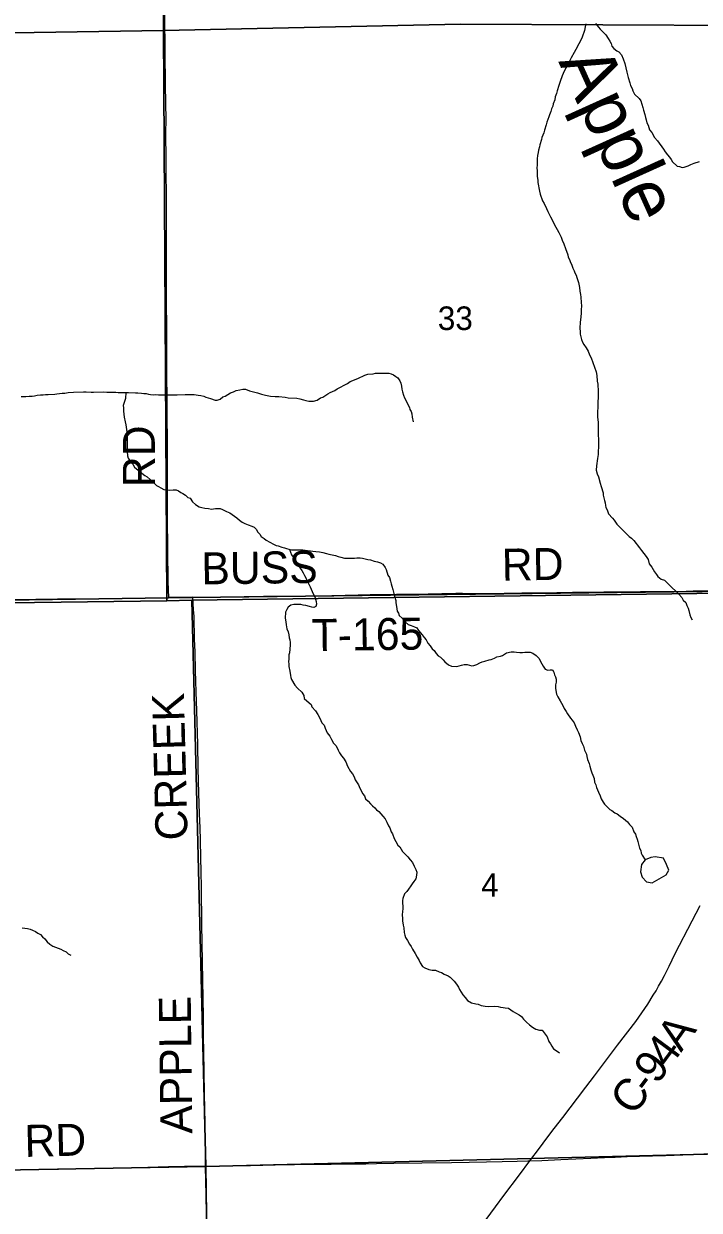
# Model space of a CAD drawing. Extents: x 1985906 to 2360102, y 891258 to 1222054.
# Drawn here: x 2149073 to 2155412, y 987975 to 999101 of the extents above; entities that cross this region are included whole.
import ezdxf

# ---------------------------------------------------------------- set-up
doc = ezdxf.new("R2010")
doc.units = 0
for name, color, linetype in [('GM_X_County_Road', 7, 'Continuous'), ('GM_X_County_Road_Text', 7, 'Continuous'), ('GM_X_Minor_Lake', 7, 'Continuous'), ('GM_X_Minor_River', 7, 'Continuous'), ('GM_X_Minor_River_Text', 7, 'Continuous'), ('GM_X_Section', 7, 'Continuous'), ('GM_X_Section_Text', 7, 'Continuous'), ('GM_X_Township', 7, 'Continuous'), ('GM_X_Township_Road', 7, 'Continuous'), ('GM_X_Township_Road_Text', 7, 'Continuous')]:
    doc.layers.add(name, color=color, linetype=linetype)

msp = doc.modelspace()

# ---------------------------------------------------------------- linework, layer by layer
at = {"layer": 'GM_X_County_Road'}
for points in [[(2150433, 993720), (2150428, 993869), (2150426, 994164), (2150423, 994476), (2150422, 994673), (2150422, 994820), (2150421, 994951), (2150421, 995033), (2150421, 995181), (2150418, 995427), (2150419, 995509), (2150419, 995607), (2150417, 995788), (2150417, 995935), (2150416, 996116), (2150413, 996624), (2150413, 996985), (2150411, 997116), (2150412, 997248), (2150411, 997510), (2150409, 997690), (2150409, 997838), (2150407, 998067), (2150408, 998214), (2150406, 998345), (2150403, 998542), (2150402, 998643), (2150401, 998718), (2150401, 998802), (2150400, 998895), (2150400, 998937), (2150398, 999082), (2150396, 999279)], [(2150661, 993723), (2150570, 993722), (2150439, 993720), (2150433, 993720)], [(2150779, 988390), (2150777, 988544), (2150775, 988675), (2150774, 988790), (2150769, 989068), (2150767, 989281), (2150763, 989461), (2150761, 989610), (2150758, 989790), (2150754, 990134), (2150748, 990479), (2150745, 990659), (2150740, 991003), (2150737, 991151), (2150734, 991281), (2150730, 991445), (2150727, 991560), (2150722, 991691), (2150717, 991887), (2150711, 992117), (2150705, 992346), (2150696, 992658), (2150690, 992838), (2150685, 993036), (2150680, 993212), (2150676, 993330), (2150671, 993542), (2150667, 993607), (2150664, 993662), (2150661, 993723)], [(2153822, 988440), (2153911, 988558), (2153981, 988650), (2154050, 988741), (2154130, 988845), (2154268, 989028), (2154348, 989130), (2154429, 989237), (2154645, 989524), (2154815, 989746), (2154872, 989826), (2154928, 989907), (2154980, 989991), (2155007, 990034), (2155029, 990076), (2155057, 990125), (2155084, 990177), (2155129, 990265), (2155187, 990383), (2155344, 990689), (2155419, 990834)], [(2153822, 988440), (2153934, 988443), (2154114, 988451), (2154393, 988464), (2154458, 988468), (2154523, 988470), (2154621, 988474), (2154735, 988478), (2154850, 988482), (2155095, 988490), (2155259, 988496), (2155456, 988504), (2155619, 988508), (2155849, 988518), (2155980, 988523), (2156229, 988529)], [(2150779, 988390), (2150956, 988393), (2151202, 988396), (2151431, 988401), (2151612, 988405), (2151710, 988408), (2151776, 988409), (2151956, 988409), (2152136, 988410), (2152218, 988411), (2152284, 988412), (2152382, 988414), (2152546, 988416), (2152808, 988419), (2153087, 988423), (2153251, 988426), (2153415, 988429), (2153562, 988432), (2153704, 988437), (2153803, 988440), (2153822, 988440)], [(2152855, 987119), (2152883, 987159), (2153063, 987413), (2153149, 987533), (2153294, 987731), (2153411, 987889), (2153500, 988008), (2153577, 988113), (2153725, 988309), (2153822, 988440)], [(2149023, 988355), (2149154, 988358), (2149399, 988362), (2149594, 988366), (2149710, 988368), (2149875, 988371), (2150022, 988374), (2150136, 988377), (2150333, 988382), (2150431, 988385), (2150580, 988388), (2150710, 988389), (2150779, 988390)], [(2150836, 984837), (2150838, 984849), (2150839, 984859), (2150840, 984877), (2150842, 985003), (2150837, 985265), (2150836, 985446), (2150835, 985577), (2150834, 985675), (2150832, 985823), (2150829, 985970), (2150821, 986314), (2150818, 986445), (2150816, 986577), (2150813, 986724), (2150808, 986888), (2150798, 987412), (2150791, 987773), (2150784, 988117), (2150782, 988249), (2150779, 988390)]]:
    msp.add_lwpolyline(points, dxfattribs=at)
at = {"layer": 'GM_X_Minor_Lake'}
for points in [[(2154904, 991262), (2154870, 991216), (2154860, 991149), (2154875, 991099), (2154917, 991056), (2154969, 991046), (2155102, 991119), (2155126, 991163), (2155104, 991217), (2155075, 991277), (2154997, 991289), (2154957, 991284)], [(2154957, 991284), (2154904, 991262)]]:
    msp.add_lwpolyline(points, dxfattribs=at)
at = {"layer": 'GM_X_Minor_River'}
for points in [[(2154347, 999101), (2154341, 999071), (2154334, 999039), (2154330, 999019), (2154320, 998995), (2154312, 998975), (2154298, 998942), (2154283, 998914), (2154253, 998858), (2154237, 998830), (2154210, 998781), (2154194, 998751), (2154158, 998685), (2154143, 998655), (2154125, 998612), (2154107, 998560), (2154094, 998522), (2154078, 998472), (2154072, 998448), (2154058, 998415), (2154055, 998389), (2154041, 998349), (2154037, 998329), (2154025, 998303), (2154019, 998279), (2154006, 998248), (2154000, 998228), (2153982, 998178), (2153974, 998154), (2153959, 998104), (2153953, 998078), (2153935, 998035), (2153931, 998015), (2153916, 997967), (2153914, 997947), (2153904, 997917), (2153900, 997895), (2153894, 997864), (2153891, 997834), (2153891, 997804), (2153889, 997774), (2153887, 997750), (2153890, 997722), (2153892, 997692), (2153892, 997668), (2153896, 997634), (2153898, 997612), (2153903, 997582), (2153905, 997561), (2153911, 997531), (2153919, 997503), (2153941, 997441), (2153956, 997415), (2153978, 997367), (2153992, 997341), (2154016, 997291), (2154033, 997255), (2154053, 997215), (2154077, 997173), (2154093, 997143), (2154116, 997099), (2154124, 997073), (2154142, 997037), (2154156, 996993), (2154177, 996933), (2154183, 996913), (2154195, 996891), (2154199, 996871), (2154216, 996837), (2154224, 996808), (2154238, 996784), (2154244, 996764), (2154256, 996742), (2154264, 996720), (2154279, 996674), (2154287, 996628), (2154291, 996594), (2154297, 996562), (2154300, 996536), (2154304, 996488), (2154306, 996456), (2154304, 996417), (2154303, 996389), (2154301, 996349), (2154295, 996303), (2154292, 996247), (2154294, 996213), (2154294, 996189), (2154306, 996140), (2154315, 996116), (2154327, 996094), (2154351, 996062), (2154369, 996032), (2154383, 995996), (2154398, 995968), (2154414, 995926), (2154444, 995836)], [(2154439, 999104), (2154467, 999070), (2154483, 999050), (2154514, 999018), (2154534, 998996), (2154556, 998962), (2154572, 998936), (2154584, 998916), (2154592, 998892), (2154609, 998868), (2154637, 998846), (2154657, 998836), (2154681, 998810), (2154697, 998772), (2154713, 998728), (2154724, 998686), (2154732, 998648), (2154744, 998596), (2154761, 998546), (2154767, 998521), (2154781, 998493), (2154787, 998473), (2154805, 998441), (2154848, 998399), (2154864, 998377), (2154874, 998347), (2154882, 998315), (2154888, 998289), (2154901, 998249), (2154907, 998223), (2154913, 998201), (2154921, 998173), (2154931, 998151), (2154946, 998107), (2154966, 998081), (2154992, 998035), (2155020, 998003), (2155035, 997981), (2155061, 997947), (2155075, 997925), (2155093, 997901), (2155113, 997873), (2155133, 997849), (2155149, 997827), (2155160, 997807), (2155204, 997767), (2155226, 997761), (2155250, 997753), (2155270, 997755), (2155306, 997770), (2155334, 997782), (2155364, 997794)], [(2155364, 997794), (2155413, 997808)], [(2149539, 995645), (2149635, 995648), (2149657, 995648), (2149705, 995646), (2149727, 995646), (2149821, 995649), (2149853, 995647), (2149938, 995645), (2149958, 995644), (2150032, 995642), (2150056, 995642), (2150122, 995640), (2150142, 995639), (2150178, 995637), (2150200, 995635), (2150220, 995633), (2150242, 995629), (2150262, 995625), (2150288, 995621), (2150312, 995623), (2150338, 995622), (2150364, 995622), (2150512, 995622), (2150588, 995625), (2150614, 995625), (2150672, 995623), (2150710, 995617), (2150734, 995614), (2150762, 995610), (2150782, 995600), (2150826, 995586), (2150868, 995572), (2150888, 995570), (2150916, 995582), (2150942, 995603), (2150964, 995609), (2151013, 995639), (2151041, 995651), (2151067, 995662), (2151101, 995668), (2151129, 995674), (2151153, 995676), (2151191, 995658), (2151267, 995641), (2151305, 995629), (2151341, 995617), (2151389, 995609), (2151433, 995607), (2151465, 995605), (2151525, 995598), (2151553, 995594), (2151635, 995590), (2151665, 995584), (2151699, 995573), (2151721, 995567), (2151749, 995561), (2151771, 995561), (2151793, 995563), (2151827, 995571), (2151859, 995594), (2151879, 995600), (2151927, 995630), (2151948, 995642), (2151992, 995662), (2152014, 995679), (2152110, 995729), (2152135, 995746), (2152207, 995776), (2152273, 995806), (2152301, 995815), (2152351, 995819), (2152373, 995825), (2152449, 995826), (2152499, 995824), (2152521, 995818), (2152543, 995810), (2152563, 995794), (2152583, 995780), (2152603, 995752), (2152611, 995730), (2152617, 995704), (2152621, 995676), (2152628, 995648), (2152636, 995618), (2152646, 995592), (2152660, 995564), (2152674, 995538), (2152693, 995504), (2152697, 995484), (2152707, 995464), (2152715, 995442), (2152719, 995413), (2152726, 995367)], [(2154444, 995836), (2154451, 995802), (2154455, 995748), (2154459, 995722), (2154462, 995654), (2154462, 995619), (2154461, 995535), (2154461, 995505), (2154457, 995461), (2154456, 995413), (2154460, 995389), (2154464, 995363), (2154462, 995338), (2154463, 995234), (2154467, 995214), (2154465, 995178), (2154466, 995130), (2154464, 995094), (2154462, 995063), (2154456, 995023), (2154447, 994957), (2154443, 994915), (2154455, 994881), (2154466, 994851), (2154482, 994793), (2154492, 994761), (2154509, 994702), (2154511, 994682), (2154523, 994632), (2154529, 994608), (2154533, 994584), (2154536, 994564), (2154546, 994544), (2154554, 994524), (2154560, 994504), (2154598, 994466), (2154614, 994446), (2154637, 994410), (2154753, 994294), (2154777, 994276), (2154798, 994254), (2154852, 994186), (2154870, 994162), (2154912, 994104), (2154931, 994076), (2154943, 994036), (2154967, 994004), (2154993, 993962), (2155010, 993938), (2155022, 993918), (2155054, 993894), (2155084, 993883), (2155126, 993843), (2155219, 993751), (2155247, 993721), (2155261, 993697), (2155285, 993673), (2155295, 993645), (2155306, 993621), (2155314, 993599), (2155322, 993559), (2155332, 993535), (2155344, 993511)], [(2149050, 995605), (2149092, 995605), (2149124, 995609), (2149152, 995609), (2149174, 995613), (2149199, 995617), (2149229, 995620), (2149255, 995622), (2149277, 995624), (2149303, 995626), (2149363, 995628), (2149383, 995632), (2149433, 995637), (2149459, 995637), (2149491, 995643), (2149539, 995645)], [(2150031, 995642), (2150029, 995586), (2150015, 995550), (2150007, 995521), (2150009, 995499), (2150010, 995467), (2150012, 995439), (2150016, 995413), (2150026, 995369), (2150031, 995339), (2150035, 995319), (2150039, 995275), (2150041, 995245), (2150043, 995218), (2150044, 995196), (2150044, 995164), (2150044, 995140), (2150042, 995112), (2150042, 995090), (2150047, 995050), (2150053, 995028), (2150075, 994996), (2150095, 994970), (2150113, 994942), (2150148, 994916), (2150180, 994888), (2150210, 994866), (2150230, 994852), (2150260, 994826), (2150294, 994796), (2150318, 994772), (2150338, 994762), (2150358, 994748), (2150387, 994733), (2150411, 994729), (2150441, 994727), (2150476, 994731), (2150504, 994729), (2150525, 994721), (2150547, 994705), (2150567, 994697), (2150591, 994680), (2150613, 994660), (2150633, 994652), (2150657, 994618), (2150685, 994592), (2150719, 994572), (2150745, 994564), (2150773, 994558), (2150807, 994554), (2150835, 994550), (2150871, 994555), (2150891, 994557), (2150915, 994555), (2150939, 994545), (2150975, 994527), (2151006, 994515), (2151030, 994499), (2151050, 994483), (2151072, 994467), (2151096, 994447), (2151122, 994427), (2151148, 994414), (2151180, 994402), (2151214, 994390), (2151236, 994382), (2151258, 994358), (2151267, 994338), (2151287, 994316), (2151301, 994294), (2151329, 994274), (2151349, 994258), (2151417, 994222), (2151441, 994210), (2151461, 994204), (2151495, 994193), (2151519, 994187), (2151539, 994179), (2151561, 994175), (2151585, 994167), (2151693, 994168), (2151737, 994162), (2151763, 994158), (2151785, 994156), (2151813, 994152), (2151847, 994150), (2151879, 994142), (2151913, 994135), (2151937, 994127), (2151967, 994121), (2151999, 994115), (2152023, 994105), (2152049, 994099), (2152083, 994091), (2152111, 994090), (2152175, 994090), (2152199, 994092), (2152229, 994092), (2152253, 994090), (2152277, 994084), (2152303, 994078)], [(2151566, 994173), (2151576, 994147), (2151586, 994121), (2151622, 994067), (2151636, 994043), (2151652, 994019), (2151681, 993975), (2151695, 993951), (2151707, 993927), (2151719, 993905), (2151729, 993881), (2151748, 993847), (2151760, 993821), (2151778, 993777), (2151806, 993717), (2151817, 993684), (2151821, 993658), (2151815, 993638), (2151795, 993626), (2151775, 993630), (2151755, 993638), (2151721, 993646), (2151695, 993650), (2151673, 993654), (2151641, 993655), (2151607, 993655), (2151579, 993649), (2151555, 993631), (2151541, 993607), (2151530, 993583), (2151526, 993528), (2151532, 993492), (2151534, 993466), (2151541, 993428), (2151553, 993398), (2151559, 993370), (2151563, 993344), (2151569, 993324), (2151572, 993300), (2151572, 993276), (2151570, 993236), (2151566, 993203), (2151560, 993183), (2151559, 993147), (2151557, 993119), (2151559, 993099), (2151561, 993075), (2151570, 993031), (2151576, 992991), (2151580, 992971), (2151586, 992951), (2151616, 992899), (2151643, 992871), (2151681, 992833), (2151701, 992803), (2151705, 992773), (2151729, 992751), (2151770, 992717), (2151776, 992697), (2151810, 992659), (2151832, 992623), (2151850, 992591), (2151871, 992547), (2151891, 992523), (2151901, 992497), (2151921, 992453), (2151946, 992421), (2151962, 992391), (2151980, 992355), (2152004, 992329), (2152024, 992291), (2152037, 992265), (2152053, 992237), (2152073, 992213), (2152095, 992179), (2152111, 992139), (2152138, 992090), (2152158, 992067), (2152174, 992038), (2152182, 992012), (2152196, 991992), (2152213, 991964), (2152227, 991932), (2152243, 991904), (2152251, 991884), (2152269, 991862), (2152279, 991832), (2152304, 991812), (2152326, 991786), (2152346, 991766), (2152366, 991750), (2152384, 991731), (2152406, 991715), (2152424, 991691), (2152442, 991671), (2152463, 991645), (2152479, 991615), (2152495, 991581), (2152507, 991561), (2152519, 991524), (2152532, 991504)], [(2152303, 994078), (2152327, 994073), (2152361, 994063), (2152393, 994055), (2152421, 994047), (2152443, 994035), (2152464, 994003), (2152474, 993983), (2152490, 993929), (2152504, 993909), (2152515, 993875), (2152519, 993849), (2152527, 993827), (2152535, 993797), (2152545, 993757), (2152552, 993733), (2152564, 993692), (2152564, 993670), (2152572, 993636), (2152576, 993594), (2152589, 993574), (2152597, 993552), (2152623, 993526), (2152653, 993494), (2152681, 993468), (2152707, 993458), (2152741, 993447), (2152761, 993437), (2152776, 993411), (2152810, 993371), (2152830, 993345), (2152850, 993323), (2152866, 993293), (2152887, 993267), (2152905, 993241), (2152925, 993223), (2152943, 993197), (2152961, 993175), (2152983, 993161), (2153007, 993137), (2153023, 993117), (2153058, 993091), (2153088, 993077), (2153134, 993075), (2153160, 993079), (2153180, 993086), (2153205, 993092), (2153233, 993092), (2153277, 993080), (2153297, 993082), (2153323, 993094), (2153353, 993109), (2153373, 993117), (2153401, 993125), (2153439, 993135), (2153459, 993141), (2153489, 993151), (2153511, 993166), (2153545, 993172), (2153566, 993178), (2153602, 993202), (2153646, 993213), (2153676, 993213), (2153698, 993209), (2153728, 993205), (2153754, 993205), (2153776, 993207), (2153800, 993209), (2153826, 993207), (2153850, 993198), (2153880, 993178), (2153908, 993150), (2153918, 993128), (2153933, 993098), (2153947, 993076), (2153965, 993050), (2153991, 993040), (2154011, 993042), (2154035, 993044), (2154047, 993022), (2154053, 992996), (2154063, 992976), (2154070, 992954), (2154070, 992928), (2154062, 992902), (2154062, 992868), (2154071, 992815), (2154085, 992789), (2154105, 992751), (2154131, 992707), (2154143, 992681), (2154164, 992653), (2154174, 992629), (2154202, 992591), (2154220, 992571), (2154238, 992545), (2154249, 992513), (2154265, 992481), (2154279, 992455), (2154293, 992415), (2154301, 992381)], [(2154301, 992381), (2154314, 992353), (2154326, 992327), (2154336, 992289), (2154352, 992251), (2154358, 992231), (2154363, 992201), (2154377, 992163), (2154385, 992139), (2154395, 992105), (2154404, 992076), (2154414, 992054), (2154424, 992024), (2154430, 991990), (2154442, 991966), (2154448, 991938), (2154467, 991896), (2154481, 991860), (2154491, 991834), (2154509, 991802), (2154522, 991782), (2154544, 991762), (2154572, 991734), (2154592, 991724), (2154620, 991702), (2154640, 991694), (2154670, 991672), (2154702, 991649), (2154737, 991617), (2154757, 991591), (2154781, 991569), (2154799, 991525), (2154813, 991503), (2154821, 991481), (2154828, 991454), (2154836, 991432), (2154840, 991408), (2154852, 991370), (2154862, 991348), (2154868, 991324), (2154877, 991304), (2154904, 991262)], [(2152532, 991504), (2152548, 991460), (2152564, 991432), (2152582, 991400), (2152602, 991382), (2152627, 991340), (2152677, 991290), (2152699, 991261), (2152721, 991237), (2152736, 991202), (2152752, 991172), (2152762, 991146), (2152758, 991118), (2152752, 991082), (2152733, 991058), (2152719, 991036), (2152705, 991016), (2152683, 990987), (2152667, 990963), (2152645, 990941), (2152630, 990899), (2152628, 990879), (2152629, 990802), (2152627, 990778), (2152625, 990746), (2152627, 990710), (2152627, 990688), (2152632, 990650), (2152638, 990624), (2152644, 990580), (2152650, 990554), (2152656, 990532), (2152673, 990504), (2152693, 990472), (2152707, 990450), (2152721, 990422), (2152745, 990382), (2152764, 990348), (2152784, 990318), (2152794, 990296), (2152814, 990262), (2152838, 990248), (2152874, 990234), (2152904, 990228), (2152938, 990228), (2152972, 990210), (2152992, 990204), (2153017, 990190), (2153055, 990175), (2153075, 990161), (2153111, 990123), (2153135, 990095), (2153151, 990067), (2153161, 990045), (2153176, 990021), (2153194, 989995), (2153214, 989971), (2153238, 989943), (2153274, 989921), (2153316, 989911), (2153338, 989907), (2153366, 989895), (2153402, 989889), (2153432, 989887), (2153488, 989888), (2153526, 989886), (2153546, 989880), (2153570, 989878), (2153590, 989874), (2153622, 989870), (2153666, 989839), (2153688, 989827), (2153721, 989807), (2153743, 989791), (2153761, 989767), (2153789, 989739), (2153819, 989713), (2153847, 989693), (2153879, 989673), (2153911, 989665), (2153939, 989663), (2153984, 989601), (2154000, 989559), (2154016, 989535), (2154028, 989513), (2154044, 989489), (2154077, 989467), (2154099, 989453)], [(2149057, 990623), (2149082, 990619), (2149107, 990617), (2149132, 990611), (2149154, 990601), (2149182, 990589), (2149204, 990573), (2149230, 990560), (2149250, 990538), (2149270, 990522), (2149294, 990492), (2149318, 990472), (2149346, 990452), (2149372, 990442), (2149421, 990422), (2149443, 990412), (2149471, 990398), (2149491, 990380), (2149515, 990366)]]:
    msp.add_lwpolyline(points, dxfattribs=at)
at = {"layer": 'GM_X_Section'}
for points in [[(2150346, 1004361), (2155778, 1004472), (2155841, 999084), (2153171, 999096), (2150384, 999036)], [(2144923, 1004275), (2150346, 1004361), (2150384, 999036), (2144919, 998954)], [(2155841, 999084), (2155863, 993765), (2150651, 993695), (2150415, 993691), (2150384, 999036), (2153171, 999096)], [(2150384, 999036), (2150415, 993691), (2145202, 993624), (2144986, 993626), (2144919, 998954)], [(2155863, 993765), (2156116, 993761), (2156248, 988519), (2150783, 988387), (2150651, 993695)], [(2150415, 993691), (2150651, 993695), (2150783, 988387), (2145383, 988288), (2145202, 993624)], [(2156248, 988519), (2156285, 983174), (2150858, 983027), (2150783, 988387)], [(2150783, 988387), (2150858, 983027), (2145516, 982922), (2145383, 988288)]]:
    msp.add_lwpolyline(points, close=True, dxfattribs=at)
at = {"layer": 'GM_X_Township'}
for points in [[(2172090, 999358), (2172123, 995677), (2172150, 993985), (2169506, 993945), (2166863, 993906), (2166552, 993914), (2165196, 993888), (2164159, 993884), (2156648, 993789), (2155970, 993782), (2150653, 993720), (2150432, 993719), (2145197, 993643), (2141215, 993611), (2141187, 998951), (2141185, 999312)], [(2167077, 972563), (2161683, 972547), (2157787, 972498), (2154662, 972434), (2154379, 972429), (2151050, 972338), (2145722, 972191), (2141722, 972086), (2141290, 972067), (2141300, 973610), (2141294, 973771), (2141297, 974770), (2141289, 979366), (2141275, 980173), (2141247, 988132), (2141211, 993531), (2141215, 993611), (2145197, 993643), (2150432, 993719), (2150653, 993720), (2155970, 993782), (2156648, 993789), (2164159, 993884)]]:
    msp.add_lwpolyline(points, dxfattribs=at)
at = {"layer": 'GM_X_Township_Road'}
for points in [[(2150661, 993723), (2150783, 993725), (2151324, 993732), (2151554, 993734), (2151718, 993737), (2151964, 993741), (2152210, 993745), (2152324, 993748), (2152423, 993749), (2152570, 993751), (2152702, 993752), (2152867, 993756), (2152996, 993759), (2153127, 993761), (2153189, 993761), (2153255, 993760), (2153352, 993760), (2153582, 993762), (2153746, 993764), (2153877, 993765), (2154074, 993768), (2154222, 993770), (2154517, 993773), (2154861, 993777), (2155025, 993778), (2155288, 993781), (2155353, 993782), (2155517, 993784)], [(2148347, 993694), (2148405, 993694), (2148684, 993699), (2148979, 993702), (2149389, 993708), (2149602, 993709), (2149815, 993712), (2150127, 993716), (2150324, 993718), (2150433, 993720)]]:
    msp.add_lwpolyline(points, dxfattribs=at)

# ---------------------------------------------------------------- texts
at = {"layer": 'GM_X_County_Road_Text'}
for s, rotation, p in [('RD', 90, (2150303, 994755)), ('CREEK', 91.4638, (2150611, 991447)), ('APPLE', 90.6711, (2150655, 988694)), ('A', 54.7755, (2155241, 989450)), ('4', 53.6061, (2155127, 989296)), ('9', 53.3032, (2155016, 989146)), ('C', 53.1941, (2154794, 988850)), ('-', 53.2172, (2154942, 989047)), ('RD', 1.4655, (2149083, 988475))]:
    msp.add_text(s, height=300, rotation=rotation, dxfattribs=at).set_placement(p)
at = {"layer": 'GM_X_Minor_River_Text'}
msp.add_text('Apple', height=500.1, rotation=294.3065, dxfattribs=at).set_placement((2154087, 998747))
at = {"layer": 'GM_X_Section_Text'}
for s, p in [('33', (2152958, 996229)), ('4', (2153365, 990915))]:
    msp.add_text(s, height=221, rotation=0, dxfattribs=at).set_placement(p)
at = {"layer": 'GM_X_Township_Road_Text'}
for s, rotation, p in [('BUSS', 0.8181, (2150741, 993843)), ('RD', 0.9639, (2153561, 993878)), ('T-165', 0.8422, (2151776, 993218))]:
    msp.add_text(s, height=300, rotation=rotation, dxfattribs=at).set_placement(p)

doc.saveas('drawing.dxf')
